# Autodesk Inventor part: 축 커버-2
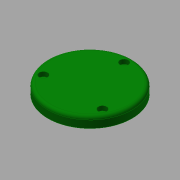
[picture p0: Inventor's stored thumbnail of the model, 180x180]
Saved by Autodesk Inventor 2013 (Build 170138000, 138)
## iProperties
Created: 2015-10
Part Number: 축 커버-2
Document SubType Name: Modeling
Designer: mdu
Density: 7.86 g/cm^3
Material: 강철, 연강
Mass: 405.676 g
Surface Area: 133.169 cm^2
Volume: 51.6127 cm^3
Author: mdu
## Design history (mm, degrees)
sketch "스케치1"
  geometry: C1 r 40 at (0, 0) reference; C2 r 26 at (0, 0) reference; 1 further point
  node "참조1"
  node "참조2"
extrude "돌출1" new body sketch "스케치1" distance "d0" = 10; taper "d1" = 0 deg
extrude "돌출2" join sketch "스케치1" distance "d2" = 3; taper "d3" = 0 deg
sketch "스케치2"
  geometry: C1 r 20 at (0, 0); 1 further point
  constraints: 1 centre point, 1 coincident
  dimensions: "d13" = 40 diameter of C1
extrude "돌출3" cut sketch "스케치2" distance "d14" = 3; taper "d15" = 0 deg
sketch "스케치3"
  geometry: C1 r 1.621 at (0, 32.5) reference; 1 further point
hole "구멍2" sketch "스케치3" at (0, 32.5) diameter "d16" = 4.5; stored, may be unused: countersink angle "d20" = 90 deg, drill point angle "d22" = 118 deg; dims "d17" = 6, "d18" = 8, "d19" = 4.4, "d21" = 8
fillet "모깎기1" dims "d26" = 3, "d27" = 0.3
chamfer "모따기1" distance "d28" = 1; stored, may be unused: second distance "d29" = 2, angle "d30" = 45 deg
node "솔리드1"
pattern_circular "원형 패턴1" dims angle "d24" = 360 deg
node "참조3"
